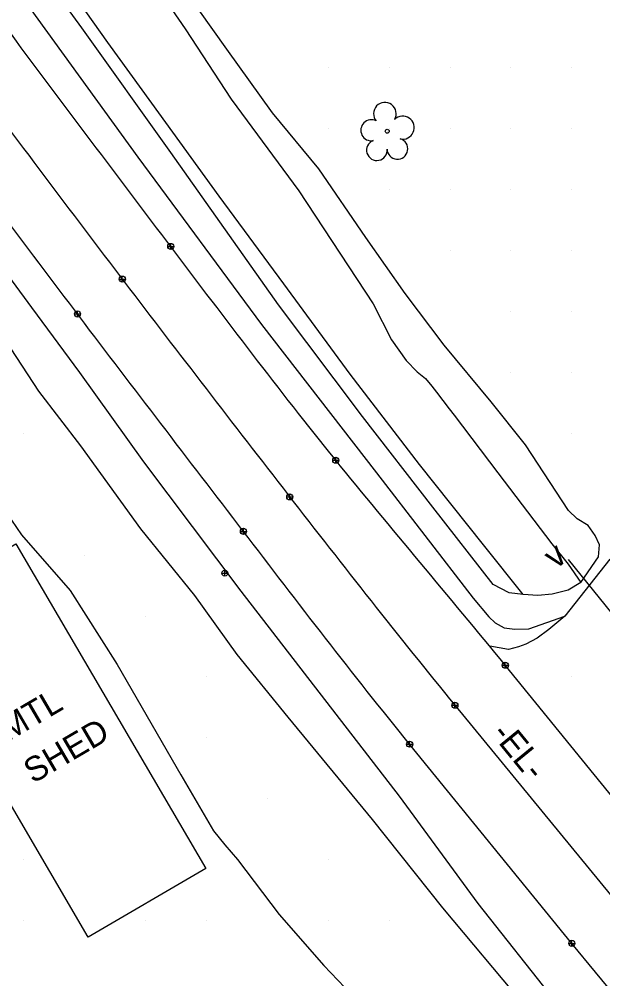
# Model space of a CAD drawing. Extents: x 1548934 to 1561348, y 809680 to 824075.
# Drawn here: x 1552189.3 to 1552285.1, y 809960.4 to 810117.9 of the extents above; entities that cross this region are included whole.
import ezdxf

# ---------------------------------------------------------------- set-up
doc = ezdxf.new("R2010")
doc.units = 0
for name, color, linetype in [('Default', 7, 'Continuous'), ('E_NCDOT_Horizontal_Alignment', 7, 'Continuous'), ('E_NCDOT_Vertical_Profile_Ground_Line', 7, 'Continuous'), ('Exist Building', 7, 'Continuous'), ('Exist Building Foundations Text', 7, 'Continuous'), ('Exist DTM QL2 LIDAR Elevation Point', 7, 'Continuous'), ('Exist Structure Minor Culvert Topo', 7, 'Continuous'), ('Exist Structure Minor Culvert Topo Terminator', 7, 'Continuous'), ('Exist Vegetation Tree CELL', 7, 'Continuous'), ('P_NCDOT_Vertical_Profile_Grade_Minor_Road', 7, 'Continuous'), ('P_RDY_Paved_Shoulder', 7, 'Continuous'), ('PH Exist DTM Breakline', 7, 'Continuous')]:
    doc.layers.add(name, color=color, linetype=linetype)

# ---------------------------------------------------------------- blocks, each defined once
blk = doc.blocks.new('SurveyPointCell')
at = {"layer": 'Default'}
for p, q in [((-0.5, 0), (0.5, 0)), ((0, -0.5), (0, 0.5))]:
    blk.add_line(p, q, dxfattribs=at)
blk.add_circle((0, 0), 0.5, dxfattribs=at)

msp = doc.modelspace()

# ---------------------------------------------------------------- linework, layer by layer
at = {"layer": 'E_NCDOT_Vertical_Profile_Ground_Line'}
for p, q in [((1552295.81, 809979.05), (1552269.12, 810011.85)), ((1552280.05, 809966.19), (1552253.41, 809998.89)), ((1552313.28, 809926), (1552280.05, 809966.19))]:
    msp.add_line(p, q, dxfattribs=at)
for points in [[(1552269.12, 810011.85), (1552259.92, 810023.16), (1552240.77, 810045.39), (1552214.34, 810080.42), (1552187.87, 810115.32), (1552162.13, 810150.99), (1552135.64, 810187.58), (1552109.72, 810225.45), (1552084.15, 810264.06), (1552058.91, 810303.06), (1552035.06, 810342.6), (1552011.64, 810381.93), (1551989.04, 810421.64), (1551966.75, 810462.54), (1551944.7, 810504.81), (1551922.38, 810547.42), (1551904.22, 810585.98), (1551891.94, 810609.51), (1551888.01, 810619.12)], [(1552253.41, 809998.89), (1552244.07, 810010.35), (1552226, 810034.01), (1552199.08, 810069.05), (1552172.73, 810104.35), (1552146.5, 810139.67), (1552120.17, 810176.34), (1552094.24, 810214.53), (1552068.08, 810253.47), (1552042.84, 810293.18), (1552018.16, 810332.72), (1551995.31, 810372.57), (1551972.35, 810412.52), (1551950.07, 810453.78), (1551927.46, 810496.24), (1551905.62, 810539.48), (1551886.94, 810576.33), (1551876.35, 810599.17), (1551872.14, 810607.03)]]:
    msp.add_open_spline(points, degree=3, dxfattribs=at)
at = {"layer": 'Exist Building'}
msp.add_lwpolyline([(1552200.63, 809967.19), (1552169.44, 810020.48), (1552188.74, 810031.78), (1552219.93, 809978.48)], close=True, dxfattribs=at)
at = {"layer": 'Exist DTM QL2 LIDAR Elevation Point'}
for p, q in [((1552240.04, 810109.94), (1552240.04, 810109.94)), ((1552250.04, 810109.94), (1552250.04, 810109.94)), ((1552260.04, 810109.94), (1552260.04, 810109.94)), ((1552270.04, 810109.94), (1552270.04, 810109.94)), ((1552280.04, 810109.94), (1552280.04, 810109.94)), ((1552240.04, 810099.94), (1552240.04, 810099.94)), ((1552250.04, 810099.94), (1552250.04, 810099.94)), ((1552260.04, 810099.94), (1552260.04, 810099.94)), ((1552270.04, 810099.94), (1552270.04, 810099.94)), ((1552280.04, 810099.94), (1552280.04, 810099.94)), ((1552250.04, 810089.94), (1552250.04, 810089.94)), ((1552260.04, 810089.94), (1552260.04, 810089.94)), ((1552270.04, 810089.94), (1552270.04, 810089.94)), ((1552280.04, 810089.94), (1552280.04, 810089.94)), ((1552260.04, 810079.94), (1552260.04, 810079.94)), ((1552270.04, 810079.94), (1552270.04, 810079.94)), ((1552280.04, 810079.94), (1552280.04, 810079.94)), ((1552270.04, 810069.94), (1552270.04, 810069.94)), ((1552280.04, 810069.94), (1552280.04, 810069.94)), ((1552270.04, 810059.94), (1552270.04, 810059.94)), ((1552280.04, 810059.94), (1552280.04, 810059.94)), ((1552190.03, 810049.94), (1552190.03, 810049.94)), ((1552280.04, 810049.94), (1552280.04, 810049.94)), ((1552200.03, 810029.93), (1552200.03, 810029.93)), ((1552210.04, 810019.93), (1552210.04, 810019.93)), ((1552220.04, 810009.93), (1552220.04, 810009.93)), ((1552280.04, 810009.93), (1552280.04, 810009.93)), ((1552220.04, 809999.93), (1552220.04, 809999.93)), ((1552230.04, 809989.93), (1552230.04, 809989.93)), ((1552190.03, 809979.93), (1552190.03, 809979.93)), ((1552240.04, 809979.93), (1552240.04, 809979.93)), ((1552190.03, 809969.93), (1552190.03, 809969.93)), ((1552210.04, 809969.93), (1552210.04, 809969.93)), ((1552220.04, 809969.93), (1552220.04, 809969.93)), ((1552240.04, 809969.93), (1552240.04, 809969.93)), ((1552250.04, 809969.93), (1552250.04, 809969.93))]:
    msp.add_line(p, q, dxfattribs=at)
at = {"layer": 'Exist Structure Minor Culvert Topo'}
msp.add_line((1552299.03, 810005.01), (1552279.48, 810029.19), dxfattribs=at)
at = {"layer": 'Exist Vegetation Tree CELL'}
msp.add_line((1552249.72, 810099.54), (1552249.72, 810099.54), dxfattribs=at)
msp.add_circle((1552249.72, 810099.54), 0.326, dxfattribs=at)
for centre, radius, start, end in [((1552249.34, 810102.41), 1.86, 330.1651, 219.7134), ((1552247.12, 810099.69), 1.73, 62.6636, 279.3457), ((1552252.27, 810100.13), 1.9, 257.1011, 134.1999), ((1552248.02, 810096.42), 1.69, 111.5671, 6.231), ((1552251.4, 810096.64), 1.7, 181.2822, 74.56)]:
    msp.add_arc(centre, radius, start, end, dxfattribs=at)
at = {"layer": 'P_NCDOT_Vertical_Profile_Grade_Minor_Road'}
msp.add_line((1552260.84, 810005.28), (1552287.66, 809972.63), dxfattribs=at)
msp.add_open_spline([(1551879.82, 810614.21), (1551884.04, 810605.38), (1551895.16, 810581.81), (1551913.82, 810543.91), (1551935.87, 810500.72), (1551958.31, 810458.4), (1551980.95, 810417.47), (1552003.45, 810377.53), (1552026.54, 810337.94), (1552050.88, 810298.39), (1552075.93, 810258.79), (1552101.83, 810219.9), (1552127.9, 810181.92), (1552154.01, 810145.19), (1552180.07, 810109.84), (1552206.52, 810074.71), (1552233.37, 810039.85), (1552251.61, 810016.53), (1552260.84, 810005.28)], degree=3, dxfattribs=at)
at = {"layer": 'P_RDY_Paved_Shoulder'}
msp.add_lwpolyline([(1552286.29, 810029.28), (1552278.9, 810019.9), (1552276.28, 810017.7), (1552274.37, 810016.31), (1552272.52, 810015.32), (1552271.31, 810014.89), (1552269.65, 810014.46), (1552266.58, 810014.96)], dxfattribs=at)
at = {"layer": 'PH Exist DTM Breakline'}
for points in [[(1552070.9, 810296.43), (1552083.99, 810275.5), (1552097.97, 810254.77), (1552110.28, 810237.04), (1552121.21, 810221.14), (1552134.52, 810200.95), (1552147.71, 810180.72), (1552163.96, 810156.98), (1552179.72, 810135.27), (1552195.09, 810114.14), (1552208.76, 810095.28), (1552229.1, 810067.78), (1552247.96, 810043.42), (1552263.84, 810022.89), (1552266.43, 810019.8), (1552267.45, 810018.79), (1552268.93, 810018), (1552270.68, 810017.79), (1552272.99, 810017.84), (1552278.9, 810019.9)], [(1552281.53, 810025.42), (1552279.45, 810024.2), (1552276.83, 810023.5), (1552274.45, 810023.31), (1552272.06, 810023.48), (1552269.75, 810023.73), (1552267.11, 810025.12), (1552257.2, 810037.79), (1552245.67, 810052.69), (1552231.88, 810071.04), (1552214.17, 810096.06), (1552199.57, 810116.5), (1552185.58, 810135.61)], [(1552205.11, 810133.01), (1552216.56, 810116.34), (1552224.09, 810104.8), (1552235.2, 810089.74), (1552247.44, 810071.2), (1552250.45, 810065.28), (1552252.85, 810061.89), (1552254.66, 810060.02), (1552256, 810058.95), (1552257.06, 810057.65), (1552257.83, 810056.67), (1552259.88, 810053.93), (1552260.72, 810052.92), (1552267.92, 810043.47), (1552276.75, 810031.79), (1552279.44, 810028.44), (1552281.53, 810025.42), (1552284.45, 810029.63), (1552284.59, 810031.6), (1552283.86, 810033.13), (1552282.72, 810034.82), (1552280.9, 810035.9), (1552279.52, 810037.26), (1552272.45, 810048.02), (1552266.82, 810055.1), (1552259.07, 810064.41), (1552252.69, 810072.9), (1552246.19, 810082.06), (1552238.5, 810093.38), (1552230.87, 810102.55), (1552223.36, 810113.03), (1552214.45, 810125.58)], [(1552272.06, 810023.48), (1552265.53, 810031.6), (1552255.03, 810044.8), (1552243.63, 810059.66), (1552232.77, 810074.5), (1552222.11, 810088.9), (1552211.08, 810104.12), (1552203.84, 810114.1), (1552195.14, 810126.42)], [(1552356.24, 809868), (1552340.53, 809884.63), (1552327.84, 809898.55), (1552316.59, 809912.56), (1552306.45, 809924.02), (1552292.89, 809939.25), (1552277.3, 809956.75), (1552264.65, 809972.75), (1552251.75, 809990.37), (1552225.73, 810024.02), (1552209.75, 810045.24), (1552199.26, 810059.94), (1552191.33, 810070.6), (1552184.93, 810079.24), (1552182.73, 810081.48), (1552180.73, 810082.53), (1552178.46, 810082.68), (1552175.3, 810082.44), (1552173.27, 810081.94), (1552169.49, 810079.05)], [(1552172.17, 810079.64), (1552172.02, 810076.34), (1552171.5, 810073.65), (1552171.32, 810070.64), (1552171.26, 810067.51), (1552175.62, 810059.63), (1552182.98, 810046.03), (1552185.98, 810038.25), (1552186.43, 810037.6), (1552188.01, 810035.65), (1552189.66, 810033.29), (1552197.66, 810024.12), (1552205.38, 810011.98), (1552215.83, 809993.87), (1552221.18, 809984.65), (1552223.03, 809982.36), (1552225.15, 809979.94), (1552231.97, 809970.94), (1552239.31, 809962.57), (1552249.67, 809951.73)], [(1552272.15, 809956.14), (1552258.88, 809972.03), (1552247.29, 809986.55), (1552233.48, 810003.34), (1552225.08, 810013.59), (1552218.13, 810023.29), (1552209.26, 810034.26), (1552199.38, 810047.9), (1552192.51, 810056.86), (1552187.02, 810065.24)]]:
    msp.add_lwpolyline(points, dxfattribs=at)

# ---------------------------------------------------------------- block references
at = {"layer": 'Default'}
for p in [(1552214.17, 810080.62), (1552206.21, 810075.25), (1552198.85, 810069.53), (1552241.28, 810045.52), (1552233.72, 810039.49), (1552226.11, 810033.84), (1552223.05, 810026.97), (1552269.12, 810011.85), (1552260.84, 810005.28), (1552253.41, 809998.89), (1552280.05, 809966.19)]:
    msp.add_blockref('SurveyPointCell', p, dxfattribs=at)

# ---------------------------------------------------------------- texts
at = {"layer": 'E_NCDOT_Horizontal_Alignment'}
msp.add_text('-EL-', height=4.02, rotation=309.2388, dxfattribs=at).set_placement((1552266.73, 810000.53))
at = {"layer": 'Exist Building Foundations Text'}
for s, p in [('MTL', (1552187.48, 809999.29)), ('SHED', (1552191.54, 809992.35))]:
    msp.add_text(s, height=4.02, rotation=30.3379, dxfattribs=at).set_placement(p)
at = {"layer": 'Exist Structure Minor Culvert Topo Terminator'}
msp.add_text('v', height=4, rotation=38.9616, dxfattribs=at).set_placement((1552277.43, 810027.52))

doc.saveas('drawing.dxf')
